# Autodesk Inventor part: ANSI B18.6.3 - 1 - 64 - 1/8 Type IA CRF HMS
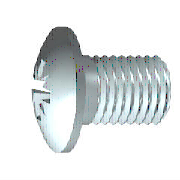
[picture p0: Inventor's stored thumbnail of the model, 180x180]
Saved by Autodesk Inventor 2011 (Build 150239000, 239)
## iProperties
IsCustomPart: 0
Created: 2008-01
Part Number: ANSI B18.6.3 - 1 - 64 - 1/8 Type IA CRF HMS
Material: Steel, Mild
Description: Cross Recessed Fillister Head Machine Screw - Type IA
Document SubType Name: Modeling
Standard: ANSI B18.6.3
Standard Revision: 2003
Standards Organization: ANSI
Language: en-US
Size Designation: 1 - 64 - 1/8
Categories: <MemberInstance><Categories><Category DisplayName="Fasteners" InternalName="e4da775c-781d-43d5-af7c-5136215cf5a6" Mnemonic="FSTN"><Category DisplayName="Bolts"
Density: 7.86 g/cm^3
Mass: 0.13629 g
Surface Area: 0.464156 cm^2
Volume: 0.0173397 cm^3
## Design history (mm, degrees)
body "Solid1"
workplane "Work Plane3"
sketch "Sketch4"
  geometry: L1 (-9, 0)-(9, 0) reference; L2 (0, -9)-(0, 9) reference; L3 (0, 0)-(6.428, 6.428); L4 (0, 0)-(6.428, -6.428); L5 (0, 0)-(-6.428, 6.428); L6 (0, 0)-(-6.428, -6.428); L7 (0.665, 0.665)-(0, 0.152); L8 (-0.665, 0.665)-(-0.152, 0); L9 (-0.665, -0.665)-(0, -0.152); L10 (0.665, -0.665)-(0.152, 0); L11 (0.665, 0.665)-(0.152, 0); L12 (-0.665, 0.665)-(0, 0.152); L13 (-0.665, -0.665)-(-0.152, 0); L14 (0.665, -0.665)-(0, -0.152); C1 r 1.499 at (0, 0) reference; A1 r 0.152 centre (0, 0) between (0, 0.152) and (-0.152, 0); A2 r 0.94 centre (0, 0) between (0.665, 0.665) and (0.665, -0.665); 1 further point
  constraints: 24 end point, 10 point on line, 7 point on circle, 3 perpendicular, 3 symmetric about line, 2 centre point, 2 coincident, 3 other
  dimensions: "d11" = 0.3048 diameter of A1 (= 0.666667 x SBR); "d14" = 45 deg angle of L3 L1; "d28" = 0.66454 distance from line of L1 L7.start (= 0.353553 x SDM)
extrude "Star Cut" cut sketch "Sketch4" distance "d12" = 1.6764 (= KOH); taper "d13" = -30 deg
sketch "Sketch2"
  geometry: L1 (-3.142, 0)-(8.365, 0) reference; L2 (0, -3.142)-(0, 8.365) reference; L3 (0, 0.94)-(0, 0); L4 (0, 0)-(0.94, 0); L5 (0, 0)-(6.721, 6.721); L6 (0.229, 0.912)-(0.137, 0.45); L7 (0.912, 0.229)-(0.45, 0.137); L8 (0.912, -0.229)-(0.45, -0.137); L9 (0.229, -0.912)-(0.137, -0.45); L10 (-0.229, 0.912)-(-0.137, 0.45); L11 (-0.912, 0.229)-(-0.45, 0.137); L12 (-0.229, -0.912)-(-0.137, -0.45); L13 (-0.912, -0.229)-(-0.45, -0.137); C1 r 1.499 at (0, 0) reference; A1 r 0.376 centre (0, 0) between (0.376, 0) and (0, 0.376); A2 r 0.121 centre (0.255, 0.426) between (0.137, 0.45) and (0.341, 0.341); A3 r 0.121 centre (0.426, 0.255) between (0.341, 0.341) and (0.45, 0.137); A4 r 0.94 centre (0, 0) between (0.94, 0) and (0.912, 0.229); A5 r 0.94 centre (0, 0) between (0.229, 0.912) and (0, 0.94); A6 r 0.94 centre (0, 0) between (0.912, 0.229) and (0.229, 0.912); A7 r 0.94 centre (0, 0) between (0, -0.94) and (0.229, -0.912); A8 r 0.94 centre (0, 0) between (0.229, -0.912) and (0.912, -0.229); A9 r 0.94 centre (0, 0) between (0.912, -0.229) and (0.94, 0); A10 r 0.121 centre (0.255, -0.426) between (0.341, -0.341) and (0.137, -0.45); A11 r 0.121 centre (0.426, -0.255) between (0.45, -0.137) and (0.341, -0.341); A12 r 0.121 centre (-0.255, 0.426) between (-0.341, 0.341) and (-0.137, 0.45); A13 r 0.121 centre (-0.426, 0.255) between (-0.45, 0.137) and (-0.341, 0.341); A14 r 0.94 centre (0, 0) between (-0.912, 0.229) and (-0.94, 0); A15 r 0.94 centre (0, 0) between (-0.229, 0.912) and (-0.912, 0.229); A16 r 0.94 centre (0, 0) between (0, 0.94) and (-0.229, 0.912); A17 r 0.94 centre (0, 0) between (-0.94, 0) and (-0.912, -0.229); A18 r 0.94 centre (0, 0) between (-0.912, -0.229) and (-0.229, -0.912); A19 r 0.94 centre (0, 0) between (-0.229, -0.912) and (0, -0.94); A20 r 0.121 centre (-0.426, -0.255) between (-0.341, -0.341) and (-0.45, -0.137); A21 r 0.121 centre (-0.255, -0.426) between (-0.137, -0.45) and (-0.341, -0.341); A22 r 0.47 centre (0, 0) between (0.47, 0) and (0, 0.47)
  constraints: 46 point on circle, 25 symmetric about line, 22 centre point, 22 end point, 6 tangent, 4 coincident, 3 collinear, 3 point on line, 1 midpoint, 1 perpendicular, 22 other
  dimensions: "d4" = 45 deg angle of L5 L4; "d5" = 0.75184 diameter of A1 (= 0.4 x SDM); "d6" = 1.8796 diameter of A6 (= SDM); "d7" = 0.2286 distance from line of L6.start L3 (= 0.5 x SBR); "d20" = 0.9398 diameter of A22 (= 0.5 x SDM)
extrude "Slot" join sketch "Sketch2" taper "d21" = 5 deg; stored distance "d54" = 10
revolve "Cut" stored, may be unused: angle "d56" = 90 deg
revolve "Body" stored, may be unused: angle "d18" = 90 deg
node "IDS_WORKPLANE{1}"
sketch "Sketch1"
  geometry: L1 (3.175, 0)-(3.175, 0.927); L2 (3.175, 0.927)-(0, 0.927); L3 (3.962, 5.08)-(3.962, 5.08); L4 (-1.676, 0)-(-1.676, 1.499); L5 (-1.484, 0.844)-(-0.732, 0.469); L6 (-0.732, 0.469)-(-0.483, 0); L7 (-0.483, 0)-(3.175, 0); L8 (-3.005, 0)-(5.124, 0) reference; L9 (0, -1.016)-(0, 6.096) reference; L10 (-1.484, 0.844)-(-1.676, 0.94); L11 (-0.973, 1.499)-(-1.676, 1.499); L12 (-0.973, 1.499)-(0, 1.499); L13 (0, 1.499)-(0, 0.927); A1 r 1.948 centre (0.272, 0) between (-0.973, 1.499) and (-1.676, 0)
  constraints: 22 end point, 4 collinear, 4 point on circle, 3 point on line, 2 parallel, 1 centre point, 1 horizontal, 1 perpendicular, 1 tangent
  dimensions: "d1" = 1.8542 diameter of L2 L7 (= GD); "d2" = 1.1938 distance from line of L6.end L4 (= STI); "d16" = 1.8796 diameter of L10.end L7 (= SDM); "d17" = 62 deg angle of L6 L7; "d19" = 26.5 deg angle of L5 L7; "d23" = 2.9972 diameter of L12.end L7 (= KOD); "d24" = 0 deg angle of L12 L7 (computed from KEWI); "d25" = 1.6764 distance between parallel lines of L4 L13 (= KOH); "d26" = 1.94818 radius of A1 (= KR); "d77" = 3.175 distance between parallel lines of L13 L1 (= NLG)
fillet "Fillet1" dims "d22" = 0.09144 (= 0.2 x SBR)
feature "Thread" dims "d8" = 2.18281 (= GEL), "d9" = 0
chamfer "Chamfer" distance "d78" = 0.19844 (= 0.5 x RR); stored, may be unused: second distance "d79" = 2, angle "d80" = 45 deg
other parameters: "GD" = 1.8542 (= NND) [user parameter; used in 1 equation term], "NLG" = 3.175 [user parameter; used in 1 equation term], "GEL" = 2.18281 [user parameter; used in 1 equation term], "KOD" = 2.9972 [user parameter; used in 3 equation terms], "KOH" = 1.6764 [user parameter; used in 3 equation terms], "SDM" = 1.8796 [user parameter; used in 5 equation terms], "STI" = 1.1938 [user parameter; used in 1 equation term], "SBR" = 0.4572 [user parameter; used in 3 equation terms], "KEWI" = 0 [user parameter; used in 1 equation term], "d3" = -1.6764 (= -KOH), "d10" = 0, "KR" = 1.94818 (= 0.65 x KOD) [user parameter; used in 1 equation term], "d75" = 0, "d76" = 0, "RR" = 0.39687 (computed from TPU) [user parameter; used in 1 equation term], "KKR" = 0.38964 (= 0.13 x KOD) [user parameter], "SPD" = 1.45733 (= GD1) [user parameter], "PTC" = 0.39687 (computed from TPU) [user parameter], "THREADDIA" = 1.8542 [user parameter], "TOA" = 30 deg [user parameter], "BDM" = 1.8542 (= NND) [user parameter], "NND" = 1.8542 [user parameter; used in 2 equation terms], "GUL" = 0 [user parameter], "GAL" = 0.39687 [user parameter], "GD1" = 1.45733 [user parameter; used in 1 equation term]
